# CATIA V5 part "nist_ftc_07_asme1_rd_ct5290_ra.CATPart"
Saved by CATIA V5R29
Part number: nist_ftc_07_asme1
Nomenclature: nist_ftc_07_asme1
Source: Unknown
Bounding box of the stored display mesh (mm): x -155.803 to 155.803, y -123.19 to 12.7, z -111.353 to 111.353
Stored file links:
  E:\users\dgn\TPS V5\Import-export annotations\Step\PMI representation 2015\NIST UC\FTC\R29\nist_ftc_07_asme1_rd - V5R29.CATPart
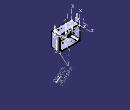
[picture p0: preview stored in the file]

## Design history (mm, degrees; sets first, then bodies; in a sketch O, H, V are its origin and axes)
TTRSSet1
f4a2d38f3ddc11d3a929006094b99c4b_11 "CATTPSSet"
Set1 "MBD_A"
  Plane1: type Offset, RefPlane face of Solid1, Offset 0, reversed
  Intersect1: ToIntersect1 edge [ZX plane of AxisSystem3 | YZ plane of AxisSystem3], ToIntersect2 Plane1
  AxisSystem1 "DBC": origin (-142.875, -104.14, 98.425), X (0, 0, 1), Y (1, 0, 0), Z (0, 1, 0)
Set2 "MBD_B"
  Sketch1 on face of Solid1, origin (0, 12.7, 0), H (-1, 0, 0), V (0, 0, 1)
    arc A1 centre (142.875, 98.425) radius 53.34 from (94.1938, 120.2262) to (117.2764, 145.221) ccw
    point P1 (117.2764, 145.221)
    point P2 (94.1938, 120.2262)
    reference projected line E2 (117.8859, 144.1068) -> (116.6669, 146.3352) from edge of Fill1
    reference projected line E3 (93.0347, 120.7453) -> (95.3528, 119.7071) from edge of Fill1
    radius A1 = 53.34
    distance P1 E2 = 0
    distance P2 E3 = 0
  Sketch2 on face of Solid1, origin (0, 12.7, 0), H (-1, 0, 0), V (0, 0, 1)
    reference projected point E1 (142.875, 98.425) from vertex [YZ plane of AxisSystem3 | ZX plane of AxisSystem3 | XY plane of AxisSystem3]
    point P1 (93.0347, 120.7453)
    point P2 (116.6669, 146.3352)
    point P3 (117.5086, 145.3842)
    point P4 (94.1938, 120.2262)
    point P5 (117.8859, 144.1068)
    line L1 (117.8859, 144.1068) -> (116.6669, 146.3352)
    point P6 (95.3528, 119.7071)
    line L2 (95.3528, 119.7071) -> (93.0347, 120.7453)
    line L3 (93.0347, 120.7453) -> (97.0262, 125.6839)
    point P7 (97.0262, 125.6839)
    line L4 (97.0262, 125.6839) -> (95.3528, 119.7071)
    line L5 (116.6669, 146.3352) -> (112.0609, 141.964)
    point P8 (112.0609, 141.964)
    line L6 (117.8859, 144.1068) -> (112.0609, 141.964)
    construction line L7 (142.875, 98.425) -> (112.3984, 154.1383)
    point P9 (112.3984, 154.1383)
    distance P3 P2 = 1.27
    length L1 = 2.54
    distance P1 P4 = 1.27
    length L2 = 2.54
    length L3 = 6.35
    length L5 = 6.35
    distance E1 P7 = 53.34
    distance E1 P8 = 53.34
    distance P5 E1 = 52.07
    distance P6 E1 = 52.07
    coincidence: E1 L2, E1 L1, L1 L7, P9 L1
    fix: L2
  Fill1: Boundary Sketch2
  Plane2: type Offset, RefPlane face of Solid1, Offset 0, reversed
  Intersect2: ToIntersect1 edge [ZX plane of AxisSystem3 | YZ plane of AxisSystem3], ToIntersect2 Plane2
  AxisSystem2 "EBC": origin (-142.875, -123.19, 98.425), X (0, 0, -1), Y (1, 0, 0), Z (0, -1, 0)
Set3 "MBD_ABCD"
  AxisSystem3 "ABC": origin (-142.875, 12.7, 98.425), X (0, 0, 1), Y (285.75, 0, 0), Z (0, 1, 0)
Body1 "Solid1" (main body)
  Solid1: solid without history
